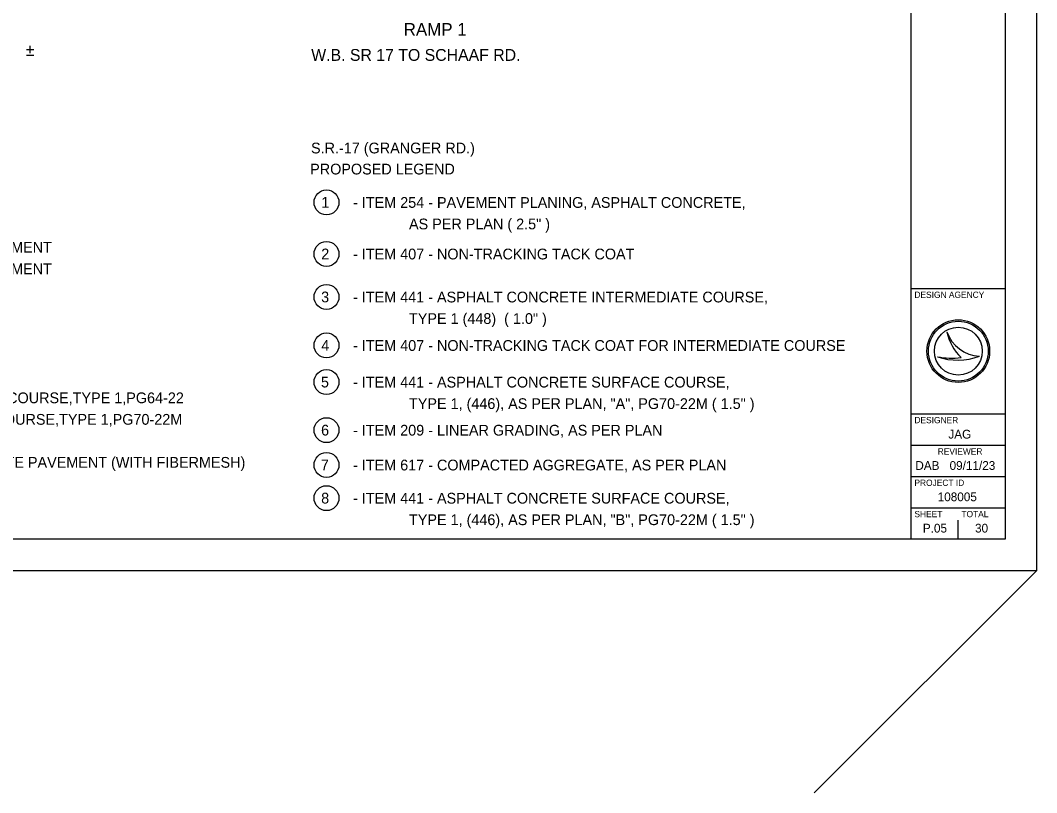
# Model space of a CAD drawing. Extents: x 227 to 993, y -530 to -180.
# Drawn here: x 670.2 to 735, y -414.1 to -364.8 of the extents above; entities that cross this region are included whole.
import ezdxf

# ---------------------------------------------------------------- set-up
doc = ezdxf.new("R2010")
doc.units = 0
for name, color, linetype in [('Default', 7, 'Continuous'), ('Level 10', 7, 'Continuous'), ('Level 59', 7, 'Continuous'), ('SC_Scratch1', 7, 'Continuous'), ('SH_Border', 7, 'Continuous'), ('SH_Cut_Line', 7, 'Continuous'), ('SH_Data', 7, 'Continuous')]:
    doc.layers.add(name, color=color, linetype=linetype)

msp = doc.modelspace()

# ---------------------------------------------------------------- linework, layer by layer
at = {"layer": 'Level 59'}
for centre in [(689.698, -376.447), (689.698, -379.739), (689.698, -382.485), (689.698, -385.577), (689.698, -387.918), (689.698, -390.987), (689.698, -393.21), (689.698, -395.328)]:
    msp.add_circle(centre, 0.795, dxfattribs=at)
at = {"layer": 'SC_Scratch1'}
msp.add_line((720.818, -414.132), (735.006, -399.944), dxfattribs=at)
at = {"layer": 'SH_Border'}
for p, q in [((727.006, -397.944), (727.006, -313.944)), ((727.006, -381.944), (733.006, -381.944)), ((727.006, -389.944), (733.006, -389.944)), ((727.006, -391.944), (733.006, -391.944)), ((727.006, -393.944), (733.006, -393.944)), ((727.006, -395.944), (733.006, -395.944))]:
    msp.add_line(p, q, dxfattribs=at)
msp.add_lwpolyline([(605.006, -313.944), (733.006, -313.944), (733.006, -397.944), (605.006, -397.944)], close=True, dxfattribs=at)
at = {"layer": 'SH_Cut_Line'}
msp.add_lwpolyline([(599.006, -399.944), (735.006, -399.944), (735.006, -311.944), (599.006, -311.944)], close=True, dxfattribs=at)
at = {"layer": 'SH_Data'}
for p, q in [((729.276, -384.706), (729.276, -384.706)), ((729.276, -384.706), (729.276, -384.706)), ((728.675, -386.306), (728.675, -386.306)), ((728.675, -386.306), (728.675, -386.306)), ((730.006, -385.944), (730.006, -385.944)), ((731.355, -386.27), (731.355, -386.27)), ((731.355, -386.27), (731.355, -386.27)), ((730.006, -397.944), (730.006, -396.744)), ((728.506, -397.244), (728.506, -397.244))]:
    msp.add_line(p, q, dxfattribs=at)
for radius in [2, 2, 1.907, 1.907, 1.907, 1.907, 1.529, 1.529]:
    msp.add_circle((730.006, -385.944), radius, dxfattribs=at)
for centre, radius, start, end in [((731.47, -383.953), 2.319, 198.92567, 198.93195), ((732.393, -384.064), 3.182, 191.63793, 191.64215), ((731.47, -383.953), 2.319, 198.93195, 267.16574), ((732.393, -384.064), 3.182, 191.64215, 226.09467), ((731.47, -383.953), 2.319, 198.92567, 198.93195), ((732.393, -384.064), 3.182, 191.63793, 191.64215), ((731.47, -383.953), 2.319, 198.93195, 267.16574), ((732.393, -384.064), 3.182, 191.64215, 226.09467), ((729.964, -382.464), 4.052, 251.45764, 290.08324), ((729.964, -382.464), 4.052, 251.45764, 290.08324), ((729.598, -381.327), 5.064, 259.49639, 259.49952), ((729.964, -382.464), 4.052, 251.45274, 251.45764), ((729.598, -381.327), 5.064, 259.49952, 276.66723), ((729.598, -381.327), 5.064, 259.49639, 259.49952), ((729.964, -382.464), 4.052, 251.45274, 251.45764), ((729.598, -381.327), 5.064, 259.49952, 276.66723)]:
    msp.add_arc(centre, radius, start, end, dxfattribs=at)

# ---------------------------------------------------------------- texts
at = {"layer": 'Default'}
msp.add_text('±', height=0.755, dxfattribs=at).set_placement((670.507, -367.094))
at = {"layer": 'Level 10'}
for s, height, p in [('RAMP 1', 0.8067, (694.623, -365.806)), ('W.B. SR 17 TO SCHAAF RD.', 0.75504, (688.723, -367.411))]:
    msp.add_text(s, height=height, dxfattribs=at).set_placement(p)
at = {"layer": 'Level 59'}
for s, height, p in [('S.R.-17 (GRANGER RD.)', 0.6864, (688.71, -373.32)), ('PROPOSED LEGEND', 0.6864, (688.655, -374.664)), ('1', 0.686, (689.366, -376.79)), ('- ITEM 254 - PAVEMENT PLANING, ASPHALT CONCRETE,', 0.6864, (691.391, -376.795)), ('              AS PER PLAN ( 2.5" )', 0.6864, (691.391, -378.168)), ('- 9" REINFORCED CONCRETE PAVEMENT', 0.6864, (653.747, -379.658)), ('2', 0.686, (689.363, -380.083)), ('- ITEM 407 - NON-TRACKING TACK COAT', 0.6864, (691.391, -380.087)), ('- 7" REINFORCED CONCRETE PAVEMENT', 0.6864, (653.747, -381.031)), ('3', 0.686, (689.355, -382.828)), ('- ITEM 441 - ASPHALT CONCRETE INTERMEDIATE COURSE,', 0.6864, (691.391, -382.833)), ('              TYPE 1 (448)  ( 1.0" )', 0.6864, (691.391, -384.206)), ('4', 0.686, (689.365, -385.92)), ('- ITEM 407 - NON-TRACKING TACK COAT FOR INTERMEDIATE COURSE', 0.6864, (691.391, -385.925)), ('5', 0.686, (689.344, -388.261)), ('- ITEM 441 - ASPHALT CONCRETE SURFACE COURSE,', 0.6864, (691.391, -388.266)), ('- 1" ITEM 448-ASPHALT CONC. INT. COURSE,TYPE 1,PG64-22', 0.6864, (653.747, -389.268)), ('              TYPE 1, (446), AS PER PLAN, "A", PG70-22M ( 1.5" )', 0.6864, (691.391, -389.638)), ('- 1.5" ASPHALT CONC. SURFACE COURSE,TYPE 1,PG70-22M', 0.6864, (653.747, -390.641)), ('6', 0.686, (689.352, -391.33)), ('- ITEM 209 - LINEAR GRADING, AS PER PLAN', 0.6864, (691.391, -391.335)), ('- 12" ITEM 452 - PLAIN MS CONCRETE PAVEMENT (WITH FIBERMESH)', 0.6864, (653.747, -393.386)), ('7', 0.686, (689.336, -393.554)), ('- ITEM 617 - COMPACTED AGGREGATE, AS PER PLAN', 0.6864, (691.391, -393.558)), ('8', 0.686, (689.357, -395.671)), ('- ITEM 441 - ASPHALT CONCRETE SURFACE COURSE,', 0.6864, (691.391, -395.676)), ('              TYPE 1, (446), AS PER PLAN, "B", PG70-22M ( 1.5" )', 0.6864, (691.391, -397.049))]:
    msp.add_text(s, height=height, dxfattribs=at).set_placement(p)
at = {"layer": 'SH_Data'}
for s, height, p in [('DESIGN AGENCY', 0.4, (727.206, -382.544)), ('DESIGNER', 0.4, (727.206, -390.544)), ('JAG', 0.56, (729.374, -391.524)), ('REVIEWER', 0.4, (728.693, -392.544)), ('09/11/23', 0.56, (729.451, -393.524)), ('DAB', 0.56, (727.265, -393.524)), ('PROJECT ID', 0.4, (727.206, -394.544)), ('108005', 0.56, (728.691, -395.524)), ('SHEET', 0.4, (727.206, -396.544)), ('TOTAL', 0.4, (730.206, -396.544)), ('P.05', 0.56, (727.745, -397.524)), ('30', 0.56, (731.074, -397.524))]:
    msp.add_text(s, height=height, dxfattribs=at).set_placement(p)

doc.saveas('drawing.dxf')
